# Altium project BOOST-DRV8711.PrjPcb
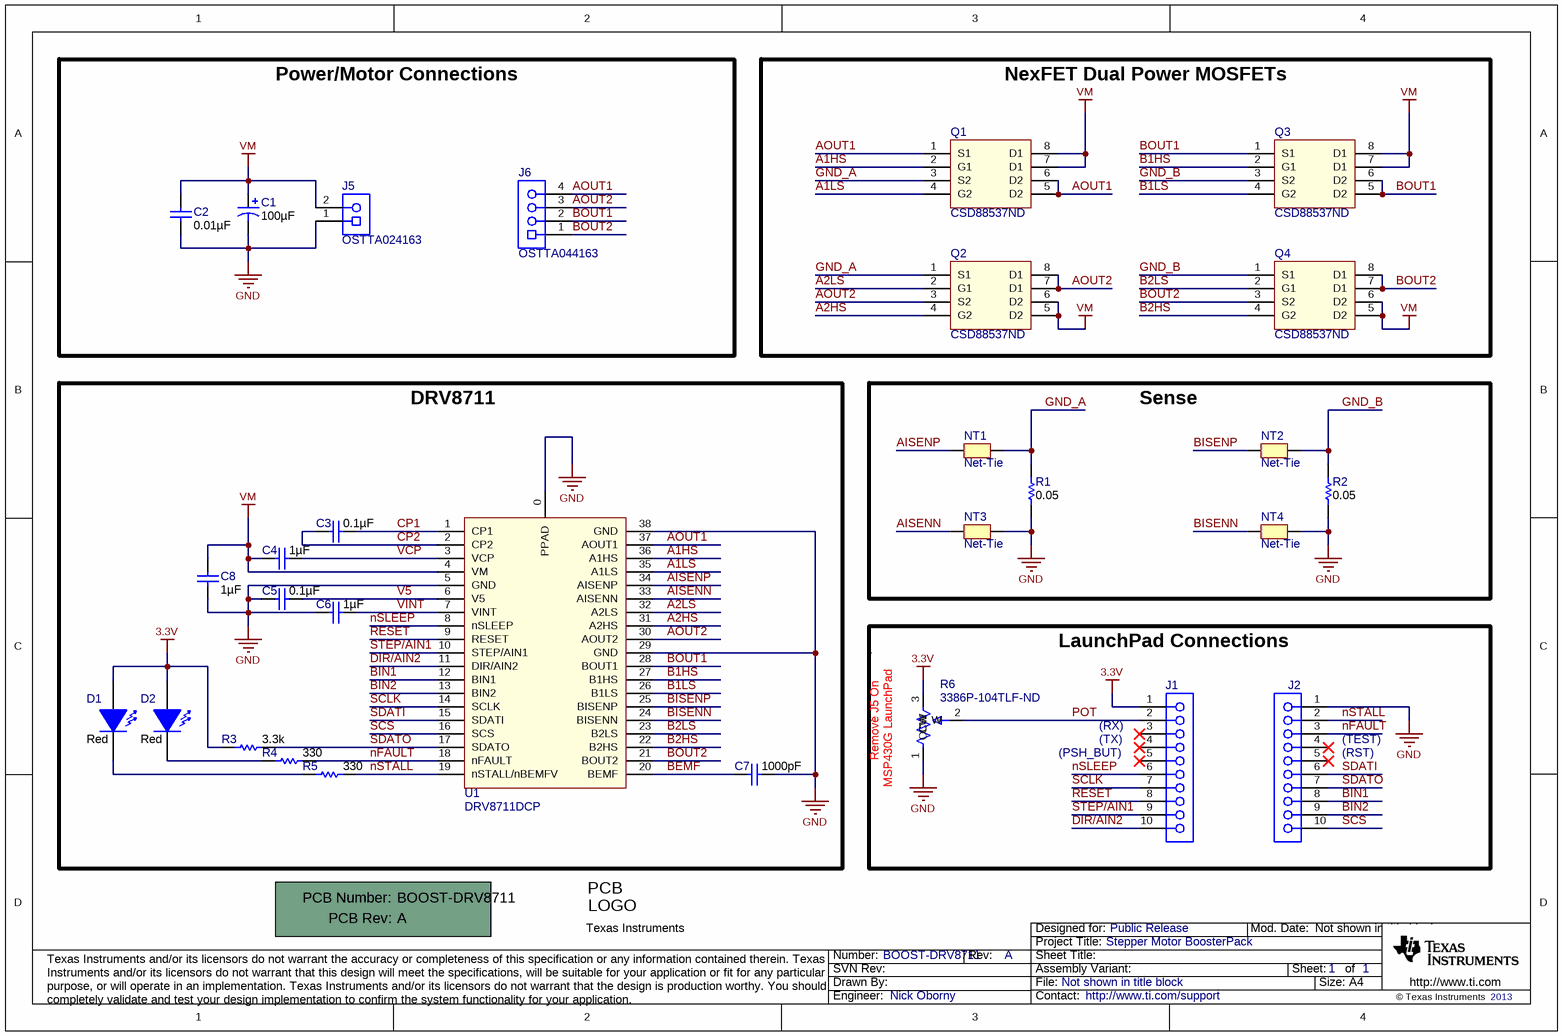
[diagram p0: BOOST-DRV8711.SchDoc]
TechSupport: http://www.ti.com/support; SCH_Rev: A; PRJ_Title: Stepper Motor BoosterPack; PRJ_Number: BOOST-DRV8711; PRJ_Engineer: Nick Oborny; PRJ_Customer: Public Release; PCB_Rev: A; PCB_Layout: Nick Oborny; CopyrightYear: 2013
1 sheet, 31 parts. Net scope: global (net labels, ports and power ports of the same name join across sheets).
Board file: BOOST-DRV8711.PcbDoc

## Sheet BOOST-DRV8711.SchDoc
size A4; Date: Not shown in title block; ApprovedBy: Not shown in title block; CheckedBy: Not shown in title block; Author: Not shown in title block; CompanyName: Not shown in title block; Engineer: Not shown in title block; Organization: Not shown in title block; Address1: Not shown in title block; Address2: Not shown in title block; Address3: Not shown in title block; Address4: Not shown in title block; DocumentNumber: 1; Revision: Use project parameter SCH_Rev; SheetNumber: 1; SheetTotal: 1; PageSetup: Record=PageOptions|CenterHorizontal=True|CenterVertical=True|PrintScale=1.00|XCorrection=1.00|YCorrection=1.00|PrintKind=0|BorderSize=5000000|LeftOffset=0|BottomOffset=0|Orientation=2|PaperLength=1000|PaperWidth=1000|Scale=100|PaperSource=15|PrintQuality=600|MediaType=1|DitherType=10|PaperKind=Letter|PrintScaleMode=1

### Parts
!PCB  Printed Circuit Board  (value not drawn)  (mechanical)
C1  ValueDisplayed: 100µF  [CAPPR5-10X20]  (hidden comment: ECA-2AM101)
C2  ValueDisplayed: 0.01µF  [0603L]  (hidden comment: C1608X7R2A103K)
C3  ValueDisplayed: 0.1µF  [0603L]  (hidden comment: GRM188R72A104KA35D)
C4  ValueDisplayed: 1µF  [0805L]  (hidden comment: CL21B105KBFNNNE)
C5  ValueDisplayed: 0.1µF  [0603L]  (hidden comment: C1608X7R1E104K)
C6  ValueDisplayed: 1µF  [0603L]  (hidden comment: C1608X7R1C105K)
C7  ValueDisplayed: 1000pF  [0603L]  (hidden comment: C0603C102K4RACTU)
C8  ValueDisplayed: 1µF  [1206L]  (hidden comment: HMK316B7105KL-T)
D1  value Red  [LED_LTST-C170]  (hidden comment: LTST-C170KRKT)
D2  value Red  [LED_LTST-C170]  (hidden comment: LTST-C170KRKT)
J1  CRD-081413-B-T  [CONN_SSW-110-23-F-S]  (value not drawn)
J2  CRD-081413-B-T  [CONN_SSW-110-23-F-S]  (value not drawn)
J5  OSTTA024163  [CONN_ED120-2DS]
J6  OSTTA044163  [CONN_ED120_4DS]
Logo1  Texas Instruments  [TI_Symbol_Overlay_Small]  (no BOM)
NT1  Net-Tie  [Net-Tie_10mil]  (net tie, no BOM)
NT2  Net-Tie  [Net-Tie_10mil]  (net tie, no BOM)
NT3  Net-Tie  [Net-Tie_10mil]  (net tie, no BOM)
NT4  Net-Tie  [Net-Tie_10mil]  (net tie, no BOM)
Q1  CSD88537ND  [SO-8]
Q2  CSD88537ND  [SO-8]
Q3  CSD88537ND  [SO-8]
Q4  CSD88537ND  [SO-8]
R1  value 0.05  [2512M]  (hidden comment: CRA2512-FZ-R050ELF)
R2  value 0.05  [2512M]  (hidden comment: CRA2512-FZ-R050ELF)
R3  value 3.3k  [0603L]  (hidden comment: CRCW06033K30JNEA)
R4  value 330  [0603L]  (hidden comment: CRCW0603330RJNEA)
R5  value 330  [0603L]  (hidden comment: CRCW0603330RJNEA)
R6  3386P-104TLF-ND  [POT_3386P]
U1  DRV8711DCP  [R-PDSO-G38]

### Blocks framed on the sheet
Power/Motor Connections: C1 C2 J5 J6
NexFET Dual Power MOSFETs: Q1-Q4
DRV8711: C3-C8 D1 D2 R3-R5 U1
Sense: NT1-NT4 R1 R2

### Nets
3.3V: D1.1(A) D2.1(A) J1.1 R3.2 R6.3(CW)
GND: C1.2(-) C2.2 C5.2 C6.2 C7.2 C8.2 J2.1 J5.1 NT3.2 NT4.2 R1.1 R2.1 R6.1(CCW) U1.0(PPAD) U1.5(GND) U1.29(GND) U1.38(GND)
VM: C1.1(+) C2.1 C4.2 C8.1 J5.2 Q1.7(D1) Q1.8(D1) Q2.5(D2) Q2.6(D2) Q3.7(D1) Q3.8(D1) Q4.5(D2) Q4.6(D2) U1.4(VM)
A1HS: Q1.2(G1) U1.36(A1HS)
A1LS: Q1.4(G2) U1.35(A1LS)
A2HS: Q2.4(G2) U1.31(A2HS)
A2LS: Q2.2(G1) U1.32(A2LS)
AISENN: NT3.1 U1.33(AISENN)
AISENP: NT1.1 U1.34(AISENP)
AOUT1: J6.4 Q1.1(S1) Q1.5(D2) Q1.6(D2) U1.37(AOUT1)
AOUT2: J6.3 Q2.3(S2) Q2.7(D1) Q2.8(D1) U1.30(AOUT2)
B1HS: Q3.2(G1) U1.27(B1HS)
B1LS: Q3.4(G2) U1.26(B1LS)
B2HS: Q4.4(G2) U1.22(B2HS)
B2LS: Q4.2(G1) U1.23(B2LS)
BEMF: C7.1 U1.20(BEMF)
BIN1: J2.8 U1.12(BIN1)
BIN2: J2.9 U1.13(BIN2)
BISENN: NT4.1 U1.24(BISENN)
BISENP: NT2.1 U1.25(BISENP)
BOUT1: J6.2 Q3.1(S1) Q3.5(D2) Q3.6(D2) U1.28(BOUT1)
BOUT2: J6.1 Q4.3(S2) Q4.7(D1) Q4.8(D1) U1.21(BOUT2)
CP1: C3.1 U1.1(CP1)
CP2: C3.2 U1.2(CP2)
DIR/AIN2: J1.10 U1.11(DIR/AIN2)
GND_A: NT1.2 Q1.3(S2) Q2.1(S1) R1.2
GND_B: NT2.2 Q3.3(S2) Q4.1(S1) R2.2
nFAULT: J2.3 R4.2 U1.18(nFAULT)
nSLEEP: J1.6 U1.8(nSLEEP)
nSTALL: J2.2 R5.1 U1.19(nSTALL/nBEMFV)
POT: J1.2 R6.2(W)
RESET: J1.8 U1.9(RESET)
SCLK: J1.7 U1.14(SCLK)
SCS: J2.10 U1.16(SCS)
SDATI: J2.6 U1.15(SDATI)
SDATO: J2.7 R3.1 U1.17(SDATO)
STEP/AIN1: J1.9 U1.10(STEP/AIN1)
V5: C5.1 U1.6(V5)
VCP: C4.1 U1.3(VCP)
VINT: C6.1 U1.7(VINT)
NetD1_2: D1.2(K) R5.2
NetD2_2: D2.2(K) R4.1

Not connected (* = marked no-connect by the designer): J1 3* 4* 5*; J2 4* 5*

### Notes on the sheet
- LaunchPad Connections
- (near R6) Remove J5 On
- (near R6) MSP430G LaunchPad
- (near J1) (PSH_BUT)
- (near J1) (RX)
- (near J1) (TX)
- (near J2) (TEST)
- (near J2) (RST)

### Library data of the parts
!PCB = PCB: Manufacturer: Any; PartNumber: BOOST-DRV8711; SymbolCreator: a0412235
C1 = EEV-FK2A101M: CAP ALUM 100UF 100V 20% RADIAL; Manufacturer: Panasonic Electronic Components; Polarized: Y; CompType: Capacitor; U/M: EA; Tolerance_%: 20; VDC_V: 100; TaMin_C: -40; TaMax_C: 85
C2 = C1608X7R2A103K: CAP, CERM, 0.01uF, 100V, +/-10%, X7R, 0603; Manufacturer: TDK; Polarized: N; CompType: Capacitor; U/M: EA; Cap_F: 0.00000001; Tolerance_%: 10; ESR_Ohm: 0.0661; Value1: 0.0661 ohm; VDC_V: 100; TaMin_C: -55; TaMax_C: 125; Cap_Case: 0603
C3 = GRM188R72A104KA35D: CAP, CERM, 0.1uF, 100V, +/-10%, X7R, 0603; Manufacturer: MuRata; Polarized: N; CompType: Capacitor; U/M: EA; Cap_F: 0.0000001; Tolerance_%: 10; Value1: Unknown; VDC_V: 100; TaMin_C: -55; TaMax_C: 125; Cap_Case: 0603
C4 = GRM21BR71H105KA12L: CAP CER 1UF 50V 10% X7R 0805; Manufacturer: Samsung Electro-Mechanics America, Inc; Polarized: N; CompType: Capacitor; U/M: EA; Cap_F: 0.000001; Tolerance_%: 10; Value1: Unknown; VDC_V: 50; TaMin_C: -55; TaMax_C: 125; Cap_Case: 0805
C5 = C1608X7R1E104K: CAP, CERM, 0.1uF, 25V, +/-10%, X7R, 0603; Manufacturer: TDK; Polarized: N; CompType: Capacitor; U/M: EA; Cap_F: 0.0000001; Tolerance_%: 10; ESR_Ohm: 0.017; Value1: 0.017 ohm; VDC_V: 25; TaMin_C: -55; TaMax_C: 125; Cap_Case: 0603
C6 = C1608X7R1C105K: CAP, CERM, 1uF, 16V, +/-10%, X7R, 0603; Manufacturer: TDK; Polarized: N; CompType: Capacitor; U/M: EA; Cap_F: 0.000001; Tolerance_%: 10; ESR_Ohm: 0.0057; Value1: 0.0057 ohm; VDC_V: 16; TaMin_C: -55; TaMax_C: 125; Cap_Case: 0603
C7 = GRM188R71C102KA01D: CAP, CERM, 1000pF, 16V, +/-10%, X7R, 0603; Manufacturer: Kemet; Polarized: N; CompType: Capacitor; U/M: EA; Cap_F: 0.000000001; Tolerance_%: 10; Value1: Unknown; VDC_V: 16; TaMin_C: -55; TaMax_C: 125; Cap_Case: 0603
C8 = GRM31CR72A105KA01L: CAP CER 1UF 100V 10% X7R 1206; Manufacturer: Taiyo Yuden; Polarized: N; CompType: Capacitor; U/M: EA; Cap_F: 0.000001; Tolerance_%: 10; Value1: Unknown; VDC_V: 100; TaMin_C: -55; TaMax_C: 125; Cap_Case: 2220
D1 D2 = LTST-C170KRKT: LED, Red, SMD; Manufacturer: Lite-On; Type: AlInGaP; Vf_V: 2; Value2: 2V; Io_A: 20; Value1: W; U/M: EA
J1 J2 = SSW-110-23-F-S: Connector, Receptacle, 100mil, 10x1, TH; Manufacturer: Major League Electronics; SymbolCreator: a0411947; U/M: EA
J5 = ED120/2DS: TERMINAL BLOCK 5.08MM VERT 2POS, TH; Manufacturer: On Shore Technology Inc; U/M: EA
J6 = ED120/4DS: Terminal Block, 4x1, 5.08mm, TH; Manufacturer: On Shore Technology Inc; SymbolCreator: a0411947; U/M: EA
Logo1 = TI_Logo: Texas Instrument Corporate Signature; SymbolCreator: codlsc
NT1-NT4 = Net-Tie: Single point connection between nets.; SymbolCreator: codlsc
Q1-Q4 = CSD88537ND: Dual 60-V N-Channel NexFET™ Power MOSFETs; Manufacturer: Texas Instruments; SymbolCreator: a0273408; CompType: Used in some BOM reports.  Useful for finding later.; U/M: EA, IN, or GM
R1 R2 = CRA2512-FZ-R050ELF: RES, 0.05 ohm, 1%, 3W, 2512; Manufacturer: Bourns; CompType: Resistor; Value_Code: R050; Tolerance_%: 1; Power_W: 3; VDC_V: 0; TempCo: 75 ppm/C; EIA_Code: E96; U/M: EA
R3 = CRCW06033K30JNEA: RES, 3.3k ohm, 5%, 0.1W, 0603; Manufacturer: Vishay-Dale; CompType: Resistor; Res_ohm: 3300; Value_Code: 3k30; Tolerance_%: 5; Power_W: 0.1; VDC_V: 75; TempCo: 200 ppm/C; EIA_Code: E24; U/M: EA
R4 R5 = CRCW0603330RJNEA: RES, 330 ohm, 5%, 0.1W, 0603; Manufacturer: Vishay-Dale; CompType: Resistor; Value_Code: 330R; Tolerance_%: 5; Power_W: 0.1; VDC_V: 75; TempCo: 200 ppm/C; EIA_Code: E24; U/M: EA
R6 = POT_3386P: TRIMMER 100K OHM 0.5W PC PIN; Manufacturer: Bourns; Area: 148225
U1 = DRV8711DCP: Stepper Motor Pre-Driver with On-Chip 1/256 Micro-Stepping Indexer and Stall Detect; Manufacturer: Texas Instruments; SymbolCreator: a0273408; CompType: Used in some BOM reports.  Useful for finding later.; U/M: EA, IN, or GM

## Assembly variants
001: all parts fitted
